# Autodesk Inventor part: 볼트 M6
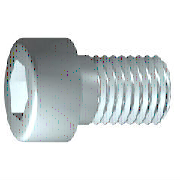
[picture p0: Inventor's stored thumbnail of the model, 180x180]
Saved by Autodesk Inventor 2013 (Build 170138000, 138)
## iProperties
IsCustomPart: 1
Created: 2012-02
Part Number: 볼트 M6
Material: 강철, 연강
Document SubType Name: Modeling
Standard: JIS B 1176
Designer: mdu-01
Standards Organization: JIS
Language: ko-KR
Size Designation: M6 x 16
Categories: <MemberInstance><Categories><Category DisplayName="조임쇠" InternalName="e4da775c-781d-43d5-af7c-5136215cf5a6" Mnemonic="FSTN"><Category DisplayName="볼트" InternalN
Density: 1 g/cm^3
Author: mdu-01
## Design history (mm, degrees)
sketch "스케치1"
  geometry: L1 (-1.333, 0)-(16, 0); L2 (16, 0)-(16, 3); L3 (16, 3)-(2.5, 3); L4 (2.5, 3)-(1.886, 3); L5 (1.886, 3)-(0, 3); L6 (0, 3)-(0, 5); L7 (0, 5)-(-6, 5); L8 (-6, 5)-(-6, 2.887); L9 (-6, 2.887)-(-3, 2.887); L10 (-3, 2.887)-(-1.333, 0); L11 (-10.4, 0)-(20.4, 0) reference; L12 (0, -1)-(0, 6) reference; L13 (2.5, 3)-(0, 3)
  constraints: 22 end point, 6 parallel, 2 collinear, 2 perpendicular, 1 horizontal, 1 point on line
  dimensions: "d1" = 13.5 distance from line of L3.end L2 (= GEL); "d2" = 0.61355 distance of L4.end L3.end (computed from GAL); "d3" = 6 distance between parallel lines of L8 L6 (= KOH); "d4" = 3 distance of L8.end L9.end (= INTI); "d5" = 60 deg angle of L10 L1; "d6" = 6 diameter of L3 L1 (= GD); "d7" = 6 diameter of L5 L1 (= BDM); "d8" = 5.7735 diameter of L9 L1 (= 1.1547 x SW); "d9" = 10 diameter of L7 L1 (= KOD); "d26" = 16 distance between parallel lines of L12 L2 (= NLG)
revolve "본체" sketch "스케치1" stored, may be unused: angle "d10" = 90 deg
sketch "스케치2"
  geometry: L1 (0, -7)-(0, 7) reference; L2 (-7, 0)-(7, 0) reference; L3 (2.887, 0)-(1.443, -2.5); L4 (1.443, -2.5)-(-1.443, -2.5); L5 (-1.443, -2.5)-(-2.887, 0); L6 (-2.887, 0)-(-1.443, 2.5); L7 (-1.443, 2.5)-(1.443, 2.5); L8 (1.443, 2.5)-(2.887, 0); 2 further points
  constraints: 12 end point, 1 coincident, 1 horizontal alignment, 1 point on line, 12 other
extrude "슬롯" join sketch "스케치2" stored distance "d11" = 10; taper "d12" = 0 deg
workplane "Work Plane1"
fillet "Fillet2" dims "d30" = 0.1 (= R)
body "Solid1"
fillet "모깎기1" dims "d17" = 0.6 (= RR)
feature "스레드" dims "d13" = 13.5 (= GEL), "d14" = 0
chamfer "모따기1" distance "d15" = 0.61345 (= -0.5 x SPD + 0.5 x GD); stored, may be unused: second distance "d16" = 0.61345 (= GUL), angle "d27" = 45 deg
other parameters: "GD" = 6 (= NND) [user parameter; used in 2 equation terms], "NLG" = 16 [user parameter; used in 1 equation term], "GEL" = 13.5 [user parameter; used in 2 equation terms], "KOD" = 10 [user parameter; used in 1 equation term], "KOH" = 6 [user parameter; used in 1 equation term], "INTI" = 3 [user parameter; used in 1 equation term], "GAL" = 0.61345 (= 0.61345 x PTC) [user parameter; used in 1 equation term], "GUL" = 0.61345 (= 0.61345 x PTC) [user parameter; used in 1 equation term], "BDM" = 6 (= NND) [user parameter; used in 1 equation term], "SW" = 5 [user parameter; used in 2 equation terms], "RR" = 0.6 [user parameter; used in 1 equation term], "SPD" = 4.7731 (= NND - 1.2269 x PTC) [user parameter; used in 1 equation term], "d19" = 0, "d28" = 0, "d29" = 0, "R" = 0.1 [user parameter; used in 1 equation term], "PHH" = 0.25 [user parameter], "GD1" = 4.7731 (= THREADDIA - 1.2269 x PTC) [user parameter], "THREADDIA" = 6 [user parameter; used in 1 equation term], "FAWI" = 45 deg [user parameter], "PTC" = 1 [user parameter; used in 5 equation terms], "NND" = 6 [user parameter; used in 3 equation terms], "TOA" = 30 deg [user parameter], "E0" = 5.775 (= 1.155 x SW) [user parameter]
